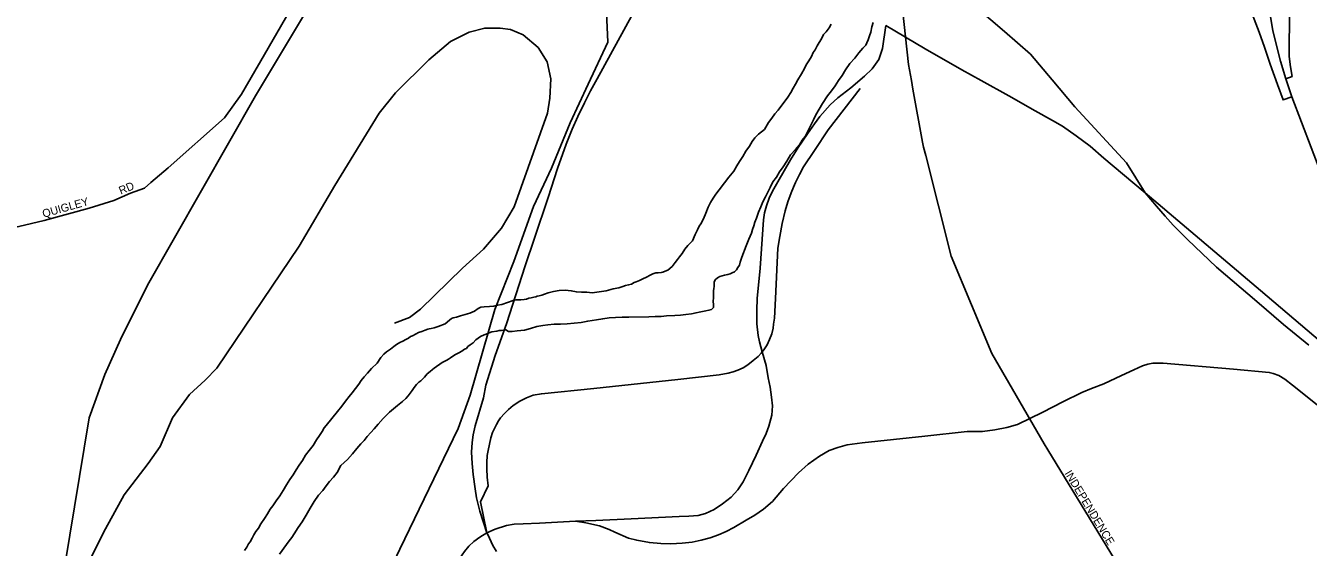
# Model space of a CAD drawing. Extents: x -561 to 1170, y 0 to 846.
# Drawn here: x 246.55 to 268.18, y 250.97 to 259.77 of the extents above; entities that cross this region are included whole.
import ezdxf

# ---------------------------------------------------------------- set-up
doc = ezdxf.new("R2010")
doc.units = 0
for name, color, linetype in [('GM_X_City_Street', 7, 'Continuous'), ('GM_X_City_Street_Text', 7, 'Continuous'), ('GM_X_Interchange_Ramps', 7, 'Continuous'), ('GM_X_Interstate_Route', 7, 'Continuous'), ('GM_X_Major_River', 7, 'Continuous'), ('GM_X_Rail_Line', 7, 'Continuous')]:
    doc.layers.add(name, color=color, linetype=linetype)

msp = doc.modelspace()

# ---------------------------------------------------------------- linework, layer by layer
at = {"layer": 'GM_X_City_Street'}
for points in [[(261.512, 258.699), (261.486, 258.845), (261.439, 259.113), (261.262, 260.726), (261.204, 262.557), (261.183, 262.952)], [(251.137, 260.26), (251.137, 260.26), (250.576, 259.284), (250.189, 258.616), (249.901, 258.213), (248.954, 257.374), (248.661, 257.122)], [(261.727, 257.581), (261.692, 257.719), (261.671, 257.802), (261.512, 258.699)], [(263.786, 252.617), (263.723, 252.72), (262.842, 254.243), (262.156, 255.883), (261.727, 257.581)], [(248.661, 257.122), (248.551, 257.028), (248.318, 256.942), (248.038, 256.822), (247.622, 256.693), (246.858, 256.484), (246.435, 256.38), (246.157, 256.328), (245.891, 256.311), (245.618, 256.295), (245.224, 256.3), (244.99, 256.311), (244.898, 256.315), (244.857, 256.317), (244.831, 256.318), (244.779, 256.321), (244.746, 256.322), (244.66, 256.364), (244.607, 256.389), (244.543, 256.44), (244.51, 256.465)], [(267.967, 248.52), (265.17, 250.442), (265.035, 250.56), (264.91, 250.772), (263.786, 252.617)]]:
    msp.add_lwpolyline(points, dxfattribs=at)
at = {"layer": 'GM_X_Interchange_Ramps'}
for points in [[(266.98, 260.988), (266.985, 260.891), (267.007, 260.728), (267.037, 260.55), (267.084, 260.366), (267.165, 260.142), (267.349, 259.658), (267.442, 259.408), (267.539, 259.119), (267.661, 258.78), (267.755, 258.516), (267.902, 258.571)], [(267.803, 258.875), (267.907, 258.913), (267.881, 259.077), (267.856, 259.25), (267.857, 259.475), (267.869, 260.13), (267.855, 260.938), (267.849, 261.041)]]:
    msp.add_lwpolyline(points, dxfattribs=at)
at = {"layer": 'GM_X_Interstate_Route'}
msp.add_lwpolyline([(269.461, 246.384), (269.45, 247.031), (269.472, 247.83), (269.535, 249.057), (269.554, 249.438), (269.59, 250.262), (269.568, 251.083), (269.487, 251.978), (269.223, 253.67), (268.998, 255.11), (268.797, 256.059), (268.555, 256.861), (267.902, 258.571), (267.803, 258.875), (267.708, 259.168), (267.579, 259.68), (267.468, 260.382), (267.409, 261.011), (267.349, 261.572)], dxfattribs=at)
at = {"layer": 'GM_X_Major_River'}
for points in [[(258.538, 255.652), (258.559, 255.69), (258.586, 255.733), (258.601, 255.782), (258.627, 255.864), (258.7, 256.054), (258.721, 256.114), (258.747, 256.169), (258.768, 256.218), (258.789, 256.272), (258.805, 256.332), (258.826, 256.392), (258.846, 256.457), (258.873, 256.522), (258.909, 256.626), (258.946, 256.713), (258.982, 256.8), (259.025, 256.882), (259.067, 256.964), (259.104, 257.04), (259.151, 257.133), (259.209, 257.215), (259.262, 257.302), (259.321, 257.389), (259.384, 257.482), (259.448, 257.591), (259.533, 257.679), (259.597, 257.761), (259.645, 257.837), (259.693, 257.903), (259.73, 257.968), (259.761, 258.034), (259.798, 258.105), (259.835, 258.181), (259.877, 258.268), (259.93, 258.361), (259.988, 258.459), (260.073, 258.585), (260.137, 258.672), (260.201, 258.754), (260.259, 258.842), (260.317, 258.929), (260.376, 259.022), (260.45, 259.131), (260.53, 259.224), (260.599, 259.312), (260.668, 259.388), (260.716, 259.438), (260.737, 259.481), (260.758, 259.53), (260.779, 259.596), (260.8, 259.661), (260.82, 259.748), (260.841, 259.824)], [(260.841, 259.824), (260.82, 259.748), (260.8, 259.661), (260.779, 259.596), (260.758, 259.53), (260.737, 259.481), (260.716, 259.438), (260.668, 259.388), (260.599, 259.312), (260.53, 259.224), (260.45, 259.131), (260.376, 259.022), (260.317, 258.929), (260.259, 258.842), (260.201, 258.754), (260.137, 258.672), (260.073, 258.585), (259.988, 258.459), (259.93, 258.361), (259.877, 258.268), (259.835, 258.181), (259.798, 258.105), (259.761, 258.034), (259.73, 257.968), (259.693, 257.903), (259.645, 257.837), (259.597, 257.761), (259.533, 257.679), (259.448, 257.591), (259.384, 257.482), (259.321, 257.389), (259.262, 257.302), (259.209, 257.215), (259.151, 257.133), (259.104, 257.04), (259.067, 256.964), (259.025, 256.882), (258.982, 256.8), (258.946, 256.713), (258.909, 256.626), (258.873, 256.522), (258.846, 256.457), (258.826, 256.392), (258.805, 256.332), (258.789, 256.272), (258.768, 256.218), (258.747, 256.169), (258.721, 256.114), (258.7, 256.054), (258.627, 255.864), (258.601, 255.782), (258.586, 255.733), (258.559, 255.69), (258.538, 255.652)], [(260.132, 259.794), (260.101, 259.734), (260.047, 259.663), (260.005, 259.619), (259.968, 259.548), (259.931, 259.488), (259.899, 259.428), (259.862, 259.362), (259.83, 259.319), (259.799, 259.248), (259.756, 259.177), (259.714, 259.111), (259.682, 259.046), (259.635, 258.959), (259.571, 258.855), (259.534, 258.784), (259.492, 258.713), (259.45, 258.642), (259.402, 258.566), (259.237, 258.347), (259.184, 258.282), (259.131, 258.21), (259.078, 258.134), (259.009, 258.019), (258.907, 257.937), (258.843, 257.876), (258.801, 257.816), (258.753, 257.735), (258.695, 257.653), (258.642, 257.565), (258.589, 257.478)], [(258.589, 257.478), (258.642, 257.565), (258.695, 257.653), (258.753, 257.735), (258.801, 257.816), (258.843, 257.876), (258.907, 257.937), (259.009, 258.019), (259.078, 258.134), (259.131, 258.21), (259.184, 258.282), (259.237, 258.347), (259.402, 258.566), (259.45, 258.642), (259.492, 258.713), (259.534, 258.784), (259.571, 258.855), (259.635, 258.959), (259.682, 259.046), (259.714, 259.111), (259.756, 259.177), (259.799, 259.248), (259.83, 259.319), (259.862, 259.362), (259.899, 259.428), (259.931, 259.488), (259.968, 259.548), (260.005, 259.619), (260.047, 259.663), (260.101, 259.734), (260.132, 259.794)], [(258.589, 257.478), (258.541, 257.407), (258.494, 257.314), (258.408, 257.216), (258.334, 257.117), (258.243, 257.002), (258.19, 256.926), (258.143, 256.86), (258.1, 256.789), (258.058, 256.708), (258.022, 256.61), (257.98, 256.512), (257.937, 256.43), (257.905, 256.386), (257.879, 256.326), (257.842, 256.245), (257.795, 256.141), (257.715, 256.064), (257.667, 255.999), (257.619, 255.928), (257.577, 255.873), (257.54, 255.824), (257.502, 255.775), (257.449, 255.709), (257.38, 255.648), (257.331, 255.632), (257.294, 255.615), (257.267, 255.604), (257.218, 255.603), (257.175, 255.603), (257.126, 255.586), (257.078, 255.564), (257.019, 255.53), (256.954, 255.502), (256.9, 255.469), (256.847, 255.447), (256.809, 255.436), (256.766, 255.408), (256.717, 255.397), (256.663, 255.385), (256.62, 255.368), (256.55, 255.346), (256.459, 255.329), (256.34, 255.3), (256.259, 255.288), (256.183, 255.276), (256.102, 255.265), (256.01, 255.274), (255.923, 255.273), (255.837, 255.278), (255.75, 255.298), (255.647, 255.308), (255.544, 255.301), (255.452, 255.284), (255.361, 255.261), (255.301, 255.239), (255.253, 255.222), (255.21, 255.216), (255.177, 255.205), (255.15, 255.199), (255.118, 255.188), (255.075, 255.182), (255.032, 255.176), (254.994, 255.159), (254.956, 255.153), (254.902, 255.147), (254.87, 255.147), (254.843, 255.147), (254.816, 255.146), (254.772, 255.135), (254.578, 255.067), (254.508, 255.056), (254.444, 255.039), (254.373, 255.033), (254.281, 255.026), (254.227, 255.02), (254.179, 254.998), (254.115, 254.954), (254.039, 254.92), (253.958, 254.897), (253.883, 254.875), (253.813, 254.852), (253.759, 254.841), (253.732, 254.83), (253.694, 254.802), (253.625, 254.742), (253.506, 254.697), (253.436, 254.675), (253.388, 254.663), (253.355, 254.657), (253.328, 254.652), (253.285, 254.635), (253.231, 254.612), (253.172, 254.595), (253.135, 254.573), (253.075, 254.54), (253.038, 254.529), (253.006, 254.501), (252.957, 254.474), (252.909, 254.446), (252.861, 254.424)], [(252.861, 254.424), (252.909, 254.446), (252.957, 254.474), (253.006, 254.501), (253.038, 254.529), (253.075, 254.54), (253.135, 254.573), (253.172, 254.595), (253.231, 254.612), (253.285, 254.635), (253.328, 254.652), (253.355, 254.657), (253.388, 254.663), (253.436, 254.675), (253.506, 254.697), (253.625, 254.742), (253.694, 254.802), (253.732, 254.83), (253.759, 254.841), (253.813, 254.852), (253.883, 254.875), (253.958, 254.897), (254.039, 254.92), (254.115, 254.954), (254.179, 254.998), (254.227, 255.02), (254.281, 255.026), (254.373, 255.033), (254.444, 255.039), (254.508, 255.056), (254.578, 255.067), (254.772, 255.135), (254.816, 255.146), (254.843, 255.147), (254.87, 255.147), (254.902, 255.147), (254.956, 255.153), (254.994, 255.159), (255.032, 255.176), (255.075, 255.182), (255.118, 255.188), (255.15, 255.199), (255.177, 255.205), (255.21, 255.216), (255.253, 255.222), (255.301, 255.239), (255.361, 255.261), (255.452, 255.284), (255.544, 255.301), (255.647, 255.308), (255.75, 255.298), (255.837, 255.278), (255.923, 255.273), (256.01, 255.274), (256.102, 255.265), (256.183, 255.276), (256.259, 255.288), (256.34, 255.3), (256.459, 255.329), (256.55, 255.346), (256.62, 255.368), (256.663, 255.385), (256.717, 255.397), (256.766, 255.408), (256.809, 255.436), (256.847, 255.447), (256.9, 255.469), (256.954, 255.502), (257.019, 255.53), (257.078, 255.564), (257.126, 255.586), (257.175, 255.603), (257.218, 255.603), (257.267, 255.604), (257.294, 255.615), (257.331, 255.632), (257.38, 255.648), (257.449, 255.709), (257.502, 255.775), (257.54, 255.824), (257.577, 255.873), (257.619, 255.928), (257.667, 255.999), (257.715, 256.064), (257.795, 256.141), (257.842, 256.245), (257.879, 256.326), (257.905, 256.386), (257.937, 256.43), (257.98, 256.512), (258.022, 256.61), (258.058, 256.708), (258.1, 256.789), (258.143, 256.86), (258.19, 256.926), (258.243, 257.002), (258.334, 257.117), (258.408, 257.216), (258.494, 257.314), (258.541, 257.407), (258.589, 257.478)], [(252.426, 252.972), (252.495, 253.049), (252.58, 253.147), (252.687, 253.251), (252.821, 253.361), (252.901, 253.433), (252.96, 253.482), (252.997, 253.526), (253.035, 253.57), (253.067, 253.619), (253.098, 253.668), (253.141, 253.717), (253.178, 253.756), (253.21, 253.778), (253.248, 253.816), (253.275, 253.844), (253.296, 253.871), (253.322, 253.898), (253.371, 253.937), (253.408, 253.97), (253.44, 253.992), (253.574, 254.091), (253.606, 254.108), (253.649, 254.13), (253.682, 254.147), (253.714, 254.169), (253.751, 254.196), (253.8, 254.224), (253.854, 254.252), (253.902, 254.279), (253.95, 254.312), (253.982, 254.324), (254.004, 254.356), (254.046, 254.389), (254.095, 254.422), (254.143, 254.472), (254.218, 254.527), (254.282, 254.555), (254.315, 254.566), (254.363, 254.588), (254.412, 254.605), (254.493, 254.617), (254.536, 254.628), (254.574, 254.629), (254.606, 254.634), (254.649, 254.64), (254.693, 254.614), (254.753, 254.609), (254.839, 254.621), (254.963, 254.633), (255.06, 254.662), (255.168, 254.695), (255.271, 254.713), (255.357, 254.725), (255.46, 254.737), (255.568, 254.733), (255.682, 254.74), (255.801, 254.752), (255.914, 254.764), (256.028, 254.787), (256.173, 254.81), (256.281, 254.828), (256.389, 254.84), (256.498, 254.847), (256.606, 254.854), (256.719, 254.855), (257.06, 254.859), (257.163, 254.866), (257.266, 254.867), (257.358, 254.874), (257.499, 254.881), (257.59, 254.887), (257.682, 254.899), (257.78, 254.911), (257.855, 254.928), (257.909, 254.94), (257.963, 254.951), (258.022, 254.963), (258.071, 254.969), (258.114, 254.98), (258.146, 255.018), (258.146, 255.062), (258.145, 255.121), (258.149, 255.181), (258.149, 255.224), (258.148, 255.251), (258.148, 255.295), (258.153, 255.338), (258.158, 255.371), (258.157, 255.409), (258.162, 255.441), (258.178, 255.485), (258.215, 255.518), (258.253, 255.54), (258.296, 255.551), (258.334, 255.562), (258.388, 255.574), (258.431, 255.585), (258.463, 255.602), (258.501, 255.619), (258.538, 255.652)], [(258.538, 255.652), (258.501, 255.619), (258.463, 255.602), (258.431, 255.585), (258.388, 255.574), (258.334, 255.562), (258.296, 255.551), (258.253, 255.54), (258.215, 255.518), (258.178, 255.485), (258.162, 255.441), (258.157, 255.409), (258.158, 255.371), (258.153, 255.338), (258.148, 255.295), (258.148, 255.251), (258.149, 255.224), (258.149, 255.181), (258.145, 255.121), (258.146, 255.062), (258.146, 255.018), (258.114, 254.98), (258.071, 254.969), (258.022, 254.963), (257.963, 254.951), (257.909, 254.94), (257.855, 254.928), (257.78, 254.911), (257.682, 254.899), (257.59, 254.887), (257.499, 254.881), (257.358, 254.874), (257.266, 254.867), (257.163, 254.866), (257.06, 254.859), (256.719, 254.855), (256.606, 254.854), (256.498, 254.847), (256.389, 254.84), (256.281, 254.828), (256.173, 254.81), (256.028, 254.787), (255.914, 254.764), (255.801, 254.752), (255.682, 254.74), (255.568, 254.733), (255.46, 254.737), (255.357, 254.725), (255.271, 254.713), (255.168, 254.695), (255.06, 254.662), (254.963, 254.633), (254.839, 254.621), (254.753, 254.609), (254.693, 254.614), (254.649, 254.64), (254.606, 254.634), (254.574, 254.629), (254.536, 254.628), (254.493, 254.617), (254.412, 254.605), (254.363, 254.588), (254.315, 254.566), (254.282, 254.555), (254.218, 254.527), (254.143, 254.472), (254.095, 254.422), (254.046, 254.389), (254.004, 254.356), (253.982, 254.324), (253.95, 254.312), (253.902, 254.279), (253.854, 254.252), (253.8, 254.224), (253.751, 254.196), (253.714, 254.169), (253.682, 254.147), (253.649, 254.13), (253.606, 254.108), (253.574, 254.091), (253.44, 253.992), (253.408, 253.97), (253.371, 253.937), (253.322, 253.898), (253.296, 253.871), (253.275, 253.844), (253.248, 253.816), (253.21, 253.778), (253.178, 253.756), (253.141, 253.717), (253.098, 253.668), (253.067, 253.619), (253.035, 253.57), (252.997, 253.526), (252.96, 253.482), (252.901, 253.433), (252.821, 253.361), (252.687, 253.251), (252.58, 253.147), (252.495, 253.049), (252.426, 252.972)], [(252.861, 254.424), (252.828, 254.407), (252.802, 254.391), (252.759, 254.357), (252.7, 254.313), (252.635, 254.269), (252.587, 254.231), (252.539, 254.171), (252.476, 254.078), (252.379, 253.99), (252.316, 253.908), (252.257, 253.848), (252.209, 253.787), (252.167, 253.722), (252.113, 253.651), (252.055, 253.58), (252.002, 253.514), (251.943, 253.438), (251.879, 253.35), (251.81, 253.263), (251.619, 253.027), (251.581, 252.989), (251.55, 252.924), (251.502, 252.858), (251.454, 252.787), (251.396, 252.689), (251.332, 252.607), (251.268, 252.525), (251.215, 252.437), (251.162, 252.355), (251.109, 252.279), (251.062, 252.197), (251.003, 252.115), (250.95, 252.028), (250.892, 251.93), (250.834, 251.842), (250.775, 251.755), (250.717, 251.673), (250.674, 251.613), (250.627, 251.536), (250.579, 251.46), (250.515, 251.367), (250.473, 251.296), (250.431, 251.236), (250.399, 251.181), (250.367, 251.127), (250.336, 251.067), (250.304, 251.029), (250.277, 250.974), (250.24, 250.919)], [(250.24, 250.919), (250.277, 250.974), (250.304, 251.029), (250.336, 251.067), (250.367, 251.127), (250.399, 251.181), (250.431, 251.236), (250.473, 251.296), (250.515, 251.367), (250.579, 251.46), (250.627, 251.536), (250.674, 251.613), (250.717, 251.673), (250.775, 251.755), (250.834, 251.842), (250.892, 251.93), (250.95, 252.028), (251.003, 252.115), (251.062, 252.197), (251.109, 252.279), (251.162, 252.355), (251.215, 252.437), (251.268, 252.525), (251.332, 252.607), (251.396, 252.689), (251.454, 252.787), (251.502, 252.858), (251.55, 252.924), (251.581, 252.989), (251.619, 253.027), (251.81, 253.263), (251.879, 253.35), (251.943, 253.438), (252.002, 253.514), (252.055, 253.58), (252.113, 253.651), (252.167, 253.722), (252.209, 253.787), (252.257, 253.848), (252.316, 253.908), (252.379, 253.99), (252.476, 254.078), (252.539, 254.171), (252.587, 254.231), (252.635, 254.269), (252.7, 254.313), (252.759, 254.357), (252.802, 254.391), (252.828, 254.407), (252.861, 254.424)], [(250.831, 250.856), (250.948, 251.02), (250.99, 251.08), (251.038, 251.14), (251.075, 251.2), (251.144, 251.304), (251.213, 251.403), (251.277, 251.512), (251.345, 251.632), (251.414, 251.746), (251.489, 251.85), (251.558, 251.932), (251.616, 252.009), (251.675, 252.08), (251.739, 252.157), (251.803, 252.233), (251.866, 252.353), (251.978, 252.452), (252.058, 252.55), (252.133, 252.638), (252.202, 252.715), (252.255, 252.775), (252.309, 252.841), (252.367, 252.906), (252.426, 252.972)], [(252.426, 252.972), (252.367, 252.906), (252.309, 252.841), (252.255, 252.775), (252.202, 252.715), (252.133, 252.638), (252.058, 252.55), (251.978, 252.452), (251.866, 252.353), (251.803, 252.233), (251.739, 252.157), (251.675, 252.08), (251.616, 252.009), (251.558, 251.932), (251.489, 251.85), (251.414, 251.746), (251.345, 251.632), (251.277, 251.512), (251.213, 251.403), (251.144, 251.304), (251.075, 251.2), (251.038, 251.14), (250.99, 251.08), (250.948, 251.02), (250.831, 250.856)]]:
    msp.add_lwpolyline(points, dxfattribs=at)
at = {"layer": 'GM_X_Rail_Line'}
for points in [[(250.424, 258.587), (255.419, 266.913), (255.688, 267.462), (256.064, 268.473)], [(265.429, 256.949), (265.111, 257.454), (264.245, 258.401), (263.862, 258.858), (263.492, 259.288), (263.055, 259.669), (262.366, 260.267), (261.647, 260.93)], [(249.965, 244.988), (250.527, 246.012), (252.857, 250.943), (253.84, 252.977), (254.042, 253.54), (254.461, 254.984), (254.779, 255.793), (255.111, 256.717), (255.414, 257.367), (255.731, 258.133), (256.035, 258.782), (256.367, 259.49), (256.319, 260.503)], [(257.121, 260.581), (256.186, 258.875), (256.073, 258.67), (255.974, 258.47), (255.858, 258.24), (255.766, 258.025), (255.664, 257.769), (255.515, 257.362), (255.359, 256.873), (255.128, 256.183), (254.972, 255.717), (254.655, 254.742), (254.469, 254.206), (254.311, 253.705), (254.271, 253.495), (254.129, 253.021), (254.093, 252.868), (254.077, 252.741), (254.067, 252.576), (254.078, 252.386), (254.097, 252.202), (254.127, 251.958), (254.152, 251.809), (254.206, 251.583), (254.324, 251.217)], [(247.617, 250.736), (247.894, 251.284), (248.208, 251.856), (248.617, 252.386), (248.816, 252.675), (249.027, 253.157), (249.31, 253.549), (249.575, 253.79), (249.774, 253.994), (251.159, 256.048), (251.762, 257.072), (252.509, 258.295), (252.786, 258.638), (253.346, 259.192), (253.714, 259.5), (254.027, 259.662), (254.292, 259.728), (254.551, 259.728), (254.725, 259.704), (254.936, 259.614), (255.189, 259.403), (255.345, 259.162), (255.406, 258.872), (255.387, 258.547), (255.351, 258.294), (254.785, 256.716), (254.574, 256.354), (254.267, 255.999), (253.917, 255.68), (253.206, 254.987), (253.02, 254.849), (252.767, 254.753)], [(261.056, 259.77), (260.999, 259.382), (260.937, 259.201), (260.823, 259.043), (260.697, 258.916), (260.466, 258.721), (260.245, 258.555), (260.117, 258.432), (259.944, 258.239), (259.853, 258.114), (259.734, 257.946), (259.579, 257.717), (259.446, 257.507), (259.233, 257.137), (259.143, 256.979), (259.088, 256.863), (259.042, 256.73), (259.011, 256.614), (258.989, 256.494), (258.934, 255.682), (258.886, 255.166), (258.881, 254.972), (258.88, 254.742), (258.903, 254.546), (258.926, 254.435), (258.968, 254.269)], [(261.056, 259.77), (261.716, 259.38), (262.339, 259.022), (262.665, 258.845), (263.127, 258.584), (263.572, 258.331), (263.864, 258.171), (264.034, 258.073), (264.265, 257.91), (264.499, 257.735), (264.732, 257.536), (265.219, 257.127), (265.429, 256.949)], [(246.864, 246.298), (246.784, 246.839), (246.748, 247.624), (246.766, 248.124), (246.881, 248.688), (247.619, 253.155), (247.881, 253.888), (248.148, 254.476), (248.604, 255.395), (250.424, 258.587)], [(260.623, 258.709), (260.083, 258.014), (259.853, 257.666), (259.669, 257.387), (259.601, 257.258), (259.532, 257.122), (259.498, 257.044), (259.458, 256.948), (259.403, 256.797), (259.357, 256.645), (259.309, 256.432), (259.267, 256.214), (259.236, 256.019), (259.196, 255.17), (259.177, 254.839), (259.162, 254.737), (259.153, 254.668), (259.13, 254.574), (259.092, 254.476), (259.051, 254.389), (258.996, 254.303), (258.968, 254.269)], [(268.186, 254.381), (267.76, 254.73), (267.312, 255.119), (266.634, 255.696), (266.144, 256.165), (265.903, 256.406), (265.768, 256.558), (265.618, 256.725), (265.429, 256.949)], [(265.429, 256.949), (267.371, 255.305), (268.499, 254.345)], [(259.127, 254.856), (259.127, 254.856)], [(258.968, 254.269), (258.952, 254.249), (258.9, 254.191), (258.82, 254.123), (258.729, 254.052), (258.647, 254), (258.559, 253.959), (258.478, 253.929), (258.395, 253.907), (258.244, 253.88), (257.545, 253.805), (256.132, 253.653), (255.247, 253.561), (255.11, 253.536), (254.995, 253.494), (254.884, 253.439), (254.772, 253.362), (254.692, 253.298), (254.622, 253.23), (254.559, 253.158), (254.525, 253.104), (254.488, 253.041), (254.454, 252.974), (254.424, 252.91), (254.392, 252.82), (254.369, 252.712), (254.347, 252.604), (254.333, 252.522), (254.324, 252.404), (254.325, 252.295), (254.329, 252.156), (254.347, 252.008), (254.217, 251.739), (254.324, 251.217)], [(258.968, 254.269), (259.038, 254.036), (259.073, 253.829), (259.104, 253.672), (259.125, 253.502), (259.144, 253.36), (259.13, 253.202), (259.082, 253.017), (259.038, 252.892), (258.973, 252.76), (258.867, 252.527), (258.747, 252.27), (258.647, 252.074), (258.557, 251.944), (258.447, 251.817), (258.302, 251.705), (258.161, 251.612), (258.016, 251.541), (257.891, 251.507), (257.733, 251.5), (257.572, 251.49), (256.761, 251.454), (256.166, 251.423), (255.821, 251.411)], [(255.821, 251.411), (255.997, 251.383), (256.225, 251.335), (256.387, 251.274), (256.485, 251.228), (256.714, 251.129), (256.853, 251.092), (257.067, 251.052), (257.259, 251.036), (257.431, 251.033), (257.618, 251.042), (257.788, 251.061), (257.94, 251.092), (258.093, 251.134), (258.231, 251.18), (258.36, 251.236), (258.493, 251.307), (258.702, 251.431), (258.843, 251.516), (258.994, 251.617), (259.144, 251.745), (259.33, 251.963), (259.582, 252.228), (259.747, 252.372), (259.937, 252.51), (260.098, 252.603), (260.245, 252.658), (260.404, 252.7), (260.657, 252.733), (261.711, 252.846), (262.428, 252.923), (262.685, 252.925), (262.892, 252.956), (263.095, 252.994), (263.273, 253.041), (263.7, 253.254), (264.038, 253.425), (264.36, 253.581), (264.526, 253.649), (264.734, 253.73), (265.032, 253.869), (265.24, 253.968), (265.384, 254.031), (265.475, 254.063), (265.56, 254.077), (265.639, 254.078), (265.73, 254.077), (266.92, 253.976), (267.52, 253.921), (267.587, 253.906), (267.684, 253.867), (267.783, 253.807), (267.914, 253.706), (268.413, 253.307)], [(254.324, 251.217), (254.466, 251.28), (254.657, 251.342), (254.788, 251.362), (254.938, 251.37), (255.215, 251.381), (255.821, 251.411)], [(254.324, 251.217), (254.21, 251.142), (254.107, 251.068), (254.024, 250.99), (253.95, 250.904), (253.871, 250.79), (253.802, 250.687), (253.748, 250.555), (253.699, 250.386), (253.627, 250.253), (253.506, 250.078), (253.367, 249.936), (253.267, 249.801), (253.212, 249.691), (253.14, 249.495), (253.001, 249.16), (252.213, 247.679), (251.547, 246.725), (250.659, 245.659), (249.965, 244.988)], [(254.324, 251.217), (254.34, 251.187), (254.428, 251.002), (254.487, 250.899)]]:
    msp.add_lwpolyline(points, dxfattribs=at)

# ---------------------------------------------------------------- texts
at = {"layer": 'GM_X_City_Street_Text'}
for s, rotation, p in [('RD', 22.3821, (248.153, 256.919)), ('QUIGLEY', 15.8183, (246.851, 256.529)), ('INDEPENDENCE', 301.1488, (264.064, 252.221))]:
    msp.add_text(s, height=0.135, rotation=rotation, dxfattribs=at).set_placement(p)

doc.saveas('drawing.dxf')
